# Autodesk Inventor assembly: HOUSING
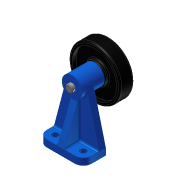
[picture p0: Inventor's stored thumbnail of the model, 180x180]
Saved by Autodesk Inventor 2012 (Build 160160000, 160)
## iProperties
Created: 2010-10
Part Number: HOUSING
Document SubType Name: Assembly
Designer: JSSONG
Mass: 273.654 g
Surface Area: 646.968 cm^2
Volume: 273.654 cm^3
Density: 1 g/cm^3
Author: JSSONG
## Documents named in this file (5)
- C:\Users\jssong\Desktop\Inventor 2012 Manual Final\EDNC_3D Inventor Modeling Tutorial\EDNC_HOUSING_Assembly Modeling\EDNC_HOUSING_Assembly.iam
- C:\Users\jssong\Desktop\Inventor 2012 Manual Final\EDNC_3D Inventor Modeling Tutorial\EDNC_HOUSING_Assembly Modeling\EDNC_Housing.ipt
- C:\Users\jssong\Desktop\Inventor 2012 Manual Final\EDNC_3D Inventor Modeling Tutorial\EDNC_HOUSING_Assembly Modeling\EDNC_Bush.ipt
- C:\Users\jssong\Desktop\Inventor 2012 Manual Final\EDNC_3D Inventor Modeling Tutorial\EDNC_HOUSING_Assembly Modeling\EDNC_Shaft.ipt
- C:\Users\jssong\Desktop\Inventor 2012 Manual Final\EDNC_3D Inventor Modeling Tutorial\EDNC_HOUSING_Assembly Modeling\EDNC_Belt Pulley.ipt
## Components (4 placed, 4 different names)
1. EDNC_Housing:1 — 플러쉬:2, 각도:1
2. EDNC_Belt Pulley:1 — 플러쉬:1
3. EDNC_Bush:1 — 플러쉬:1
4. EDNC_Shaft:1 — 플러쉬:2, 각도:1
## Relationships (3: Flush 2, Angle 1)
- 플러쉬:1 [Flush]: EDNC_Belt Pulley:1 ↔ EDNC_Bush:1
- 플러쉬:2 [Flush]: EDNC_Housing:1 ↔ EDNC_Shaft:1
- 각도:1 [Angle]: EDNC_Housing:1 ↔ EDNC_Shaft:1
